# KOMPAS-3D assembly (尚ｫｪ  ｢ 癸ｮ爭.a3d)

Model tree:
1. Эскиз:1
2. Вырезать элемент выдавливания:1
     Расстояние 1 = 10
3. Эскиз:2
     Ориентация = 2; Ориентация = 2; Ориентация = 2

Referenced files in D:\Works\UAZ\Полка\: Перед основа.m3d, Низ основа.m3d, Крышка бардачка левая.m3d, Крышка бардачка правая.m3d, Козырек в сборе.a3d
